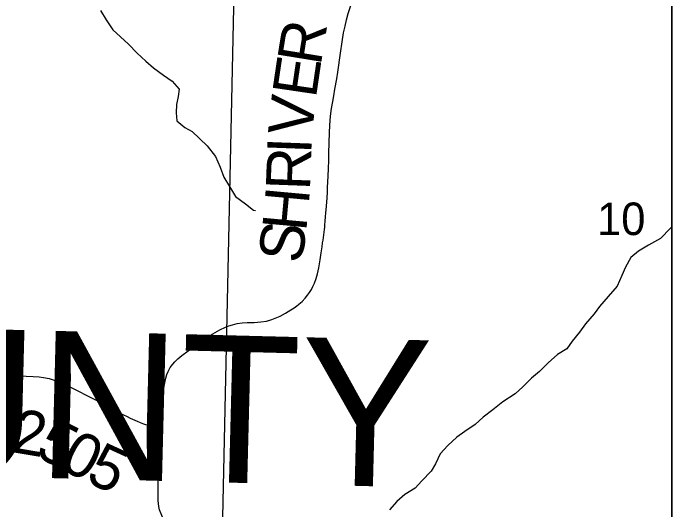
# Model space of a CAD drawing. Extents: x 0 to 34, y 0 to 22.
# Drawn here: x 7.584 to 8.431, y 20.15 to 20.789 of the extents above; entities that cross this region are included whole.
import ezdxf

# ---------------------------------------------------------------- set-up
doc = ezdxf.new("R2010")
doc.units = 0
for name, color, linetype in [('GM_X_Corporation', 7, 'Continuous'), ('GM_X_County_Road', 7, 'Continuous'), ('GM_X_County_Road_Text', 7, 'Continuous'), ('GM_X_County_Text', 7, 'Continuous'), ('GM_X_Minor_River', 7, 'Continuous'), ('GM_X_Section_Text', 7, 'Continuous'), ('GM_X_Township_Road', 7, 'Continuous'), ('GM_X_Township_Road_Text', 7, 'Continuous'), ('SH_Text', 7, 'Continuous')]:
    doc.layers.add(name, color=color, linetype=linetype)

msp = doc.modelspace()

# ---------------------------------------------------------------- linework, layer by layer
at = {"layer": 'GM_X_Corporation'}
for points in [[(4.78235, 18.12798), (4.7905, 18.36042), (4.80738, 19.54552), (4.81686, 20.04198), (4.81942, 20.1261), (5.11003, 20.11603), (6.05508, 20.08447), (6.49014, 20.07523), (6.72039, 20.06594), (7.3691, 20.05147), (7.39015, 20.05103), (7.81402, 20.04248), (8.43113, 20.02804), (8.43113, 21.3734), (1.63113, 21.3734)], [(4.05075, 18.14544), (4.78235, 18.12798), (4.7905, 18.36042), (4.80738, 19.54552), (4.81686, 20.04198), (4.81942, 20.1261), (5.11003, 20.11603), (6.05508, 20.08447), (6.49014, 20.07523), (6.72039, 20.06594), (7.3691, 20.05147), (7.39015, 20.05103), (7.81402, 20.04248), (8.43113, 20.02804), (8.43113, 21.3734), (2.79867, 21.3734)]]:
    msp.add_lwpolyline(points, dxfattribs=at)
for points in [[(7.87286, 21.05482), (7.85116, 20.0413), (6.83377, 20.06829), (6.85437, 21.08062)], [(8.43113, 20.02768), (8.43113, 21.03746), (7.87286, 21.05482), (7.85116, 20.0413)]]:
    msp.add_lwpolyline(points, close=True, dxfattribs=at)
at = {"layer": 'GM_X_County_Road'}
for points in [[(7.77292, 20.25516), (7.77358, 20.2613), (7.77443, 20.26934), (7.77517, 20.27738), (7.77587, 20.28542), (7.77685, 20.29719), (7.77782, 20.30648), (7.77888, 20.31323), (7.78024, 20.31928), (7.78163, 20.32399), (7.78344, 20.32802), (7.78604, 20.33296), (7.78925, 20.33754), (7.79164, 20.34038), (7.79556, 20.34437), (7.80078, 20.34878), (7.80879, 20.35467), (7.8179, 20.36116), (7.83073, 20.36992), (7.84068, 20.37627), (7.8498, 20.38159), (7.85705, 20.38515), (7.8611, 20.38674), (7.86584, 20.38823), (7.87185, 20.38975), (7.87862, 20.3907), (7.88481, 20.39111), (7.89406, 20.39118), (7.90248, 20.39179), (7.90994, 20.39278), (7.91411, 20.39394), (7.91645, 20.39468), (7.92717, 20.3993), (7.93423, 20.40319), (7.94115, 20.4073), (7.94532, 20.40993), (7.95068, 20.41384), (7.95139, 20.41444), (7.95352, 20.41623), (7.95576, 20.41817), (7.9596, 20.42224), (7.96267, 20.42613), (7.96517, 20.42969), (7.96746, 20.43338), (7.96948, 20.43724), (7.97145, 20.4418), (7.9736, 20.44763), (7.97534, 20.45358), (7.97708, 20.46144), (7.9789, 20.47183), (7.98016, 20.48043), (7.98128, 20.48842), (7.98195, 20.49334), (7.98248, 20.49701), (7.9842, 20.51051), (7.9846, 20.51356), (7.98489, 20.51665), (7.98534, 20.52097), (7.98585, 20.52715), (7.98622, 20.53148), (7.98691, 20.54076), (7.98771, 20.55128), (7.98812, 20.55872), (7.9884, 20.56552), (7.98867, 20.5711), (7.98935, 20.58847), (7.98975, 20.59964), (7.98995, 20.60831), (7.99031, 20.62254), (7.99067, 20.63488), (7.99114, 20.64472), (7.99211, 20.65639), (7.99349, 20.66614), (7.995, 20.67523), (7.99626, 20.68247), (7.99784, 20.69095), (8.0001, 20.7043), (8.00145, 20.71283), (8.00476, 20.73726), (8.00698, 20.75192), (8.00901, 20.76352), (8.01075, 20.77203), (8.01277, 20.78048), (8.01499, 20.78825), (8.01844, 20.79889)], [(7.81422, 20.04195), (7.81301, 20.04577), (7.81198, 20.04869), (7.80692, 20.06271), (7.80207, 20.07711), (7.79396, 20.09788), (7.79104, 20.10517), (7.78796, 20.11279), (7.78277, 20.1248), (7.77872, 20.13485), (7.77531, 20.14297), (7.77222, 20.15026), (7.77109, 20.15432), (7.7706, 20.16227), (7.77028, 20.17054), (7.77028, 20.17946), (7.77028, 20.1879), (7.7706, 20.20201), (7.77048, 20.21794), (7.77078, 20.22477), (7.77146, 20.23779), (7.77226, 20.24895), (7.77292, 20.25516)]]:
    msp.add_lwpolyline(points, dxfattribs=at)
at = {"layer": 'GM_X_Minor_River'}
for points in [[(7.69634, 20.79243), (7.70362, 20.78038), (7.71205, 20.76759), (7.72196, 20.7586), (7.73225, 20.74923), (7.74331, 20.7376), (7.75437, 20.72711), (7.76427, 20.7185), (7.7772, 20.70917), (7.78823, 20.70132), (7.79739, 20.69119), (7.79597, 20.6817), (7.79379, 20.67145), (7.7935, 20.66084), (7.79435, 20.65024), (7.80463, 20.64164), (7.81412, 20.63681), (7.83356, 20.61845), (7.84427, 20.60454), (7.85006, 20.59096), (7.85508, 20.57814), (7.86237, 20.56609), (7.87004, 20.55329), (7.8826, 20.54357), (7.89288, 20.53534), (7.89553, 20.53499)], [(8.43113, 20.5141), (8.42949, 20.51217), (8.41676, 20.49915), (8.40133, 20.49028), (8.38817, 20.48256), (8.37841, 20.4745), (8.37171, 20.46231), (8.36689, 20.45127), (8.36096, 20.43757), (8.34936, 20.42457), (8.33813, 20.41157), (8.33141, 20.40203), (8.32018, 20.38941), (8.31233, 20.37872), (8.30299, 20.36688), (8.29626, 20.35734), (8.28423, 20.35001), (8.27223, 20.33928), (8.26098, 20.32818), (8.25048, 20.31935), (8.23961, 20.30825), (8.22948, 20.29943), (8.21369, 20.28904), (8.20093, 20.27868), (8.18854, 20.26945), (8.17804, 20.25987), (8.16488, 20.25102), (8.15474, 20.24334), (8.14312, 20.23261), (8.133, 20.22227), (8.12706, 20.20933), (8.12148, 20.1998), (8.10948, 20.18755), (8.10087, 20.17799), (8.08771, 20.1699), (8.07721, 20.16069), (8.06785, 20.14999)]]:
    msp.add_lwpolyline(points, dxfattribs=at)
at = {"layer": 'GM_X_Township_Road'}
msp.add_lwpolyline([(7.57999, 20.32317), (7.5874, 20.3225), (7.60041, 20.32195), (7.60972, 20.32159), (7.61715, 20.32102), (7.6227, 20.32027), (7.63, 20.31882), (7.63537, 20.31727), (7.64062, 20.31537), (7.64578, 20.31322), (7.65086, 20.31091), (7.65589, 20.30855), (7.66862, 20.30229), (7.67689, 20.29815), (7.68294, 20.29504), (7.6879, 20.29246), (7.69395, 20.2893), (7.69893, 20.28676), (7.70165, 20.28528), (7.70992, 20.28097), (7.72241, 20.27419), (7.72507, 20.27264), (7.73064, 20.26994), (7.73443, 20.26791), (7.74343, 20.26397), (7.74714, 20.2625), (7.75151, 20.2609), (7.75858, 20.25862), (7.76515, 20.25696), (7.7693, 20.256), (7.77292, 20.25516)], dxfattribs=at)
at = {"layer": 'SH_Text'}
msp.add_line((8.43113, 21.37303), (8.43113, 14.5734), dxfattribs=at)

# ---------------------------------------------------------------- texts
at = {"layer": 'GM_X_County_Road_Text'}
for s, rotation, p in [('R', 80.76064, (7.97935, 20.72027)), ('E', 81.60898, (7.97318, 20.67845)), ('V', 84.05524, (7.96808, 20.62935)), ('I', 87.91348, (7.9673, 20.60705)), ('R', 87.88356, (7.96558, 20.56038)), ('H', 84.77414, (7.96081, 20.50722)), ('S', 81.32391, (7.95457, 20.46562))]:
    msp.add_text(s, height=0.05682, rotation=rotation, dxfattribs=at).set_placement(p)
at = {"layer": 'GM_X_County_Text'}
msp.add_text('GUERNSEY COUNTY', height=0.1893939, rotation=358.54305, dxfattribs=at).set_placement((5.55921, 20.24364))
at = {"layer": 'GM_X_Section_Text'}
msp.add_text('10', height=0.041856, rotation=0.00001, dxfattribs=at).set_placement((8.33492, 20.50347))
at = {"layer": 'GM_X_Township_Road_Text'}
for s, rotation, p in [('2', 350.40849, (7.58021, 20.22466)), ('5', 333.30229, (7.61048, 20.22022)), ('0', 332.40858, (7.64153, 20.20461)), ('5', 335.33516, (7.67539, 20.187))]:
    msp.add_text(s, height=0.05682, rotation=rotation, dxfattribs=at).set_placement(p)

doc.saveas('drawing.dxf')
